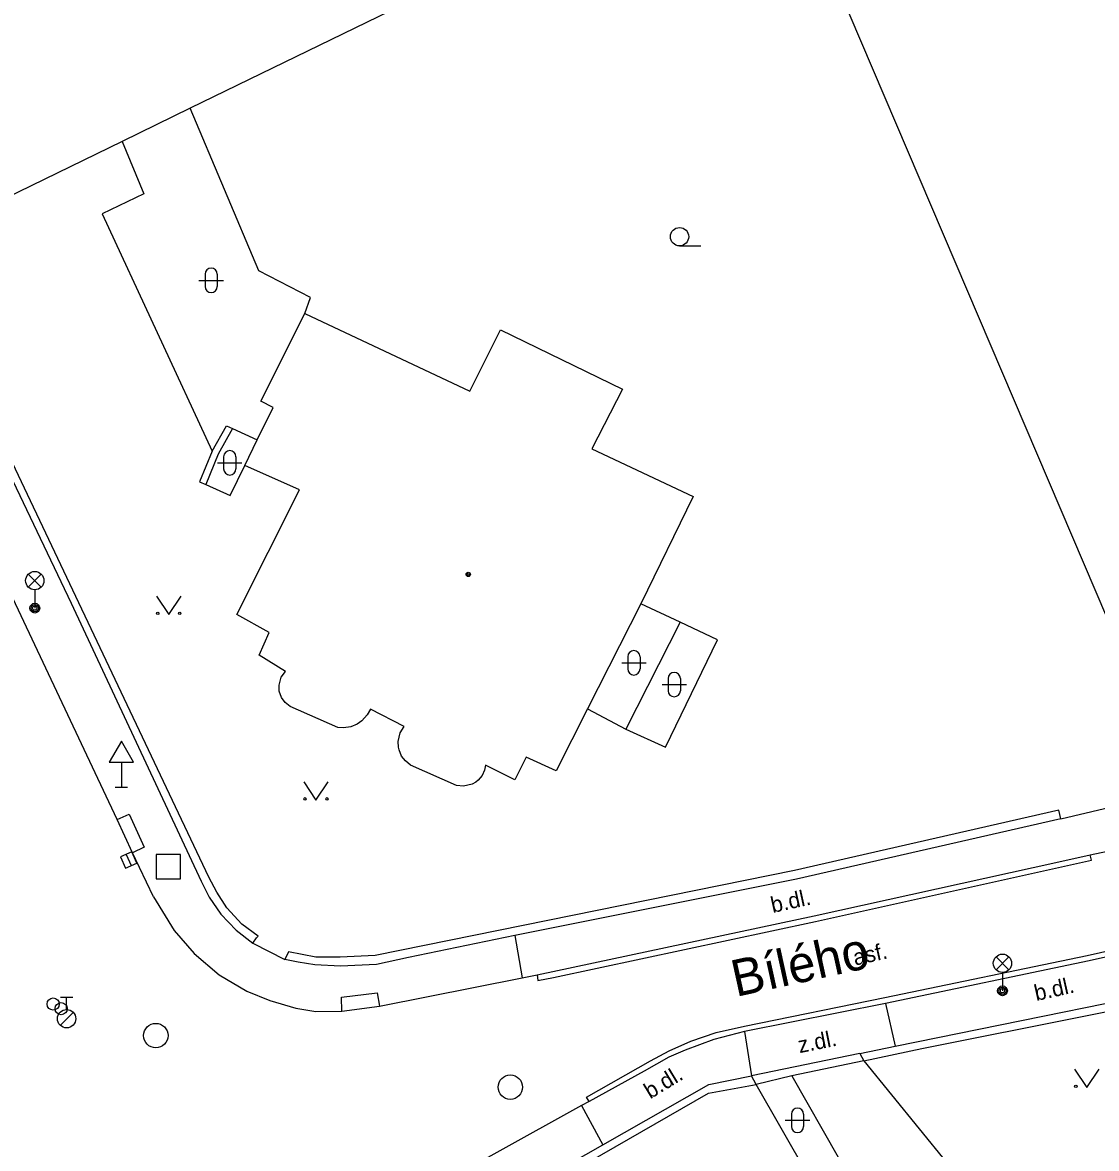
# Model space of a CAD drawing. Extents: x -600391 to -599491, y -1160176 to -1159402.
# Drawn here: x -600037.06 to -599993.14, y -1160099.55 to -1160053.5 of the extents above; entities that cross this region are included whole.
import ezdxf

# ---------------------------------------------------------------- set-up
doc = ezdxf.new("R2010")
doc.units = 0
for name, color, linetype in [('Level 10', 7, 'Continuous'), ('Level 11', 7, 'Continuous'), ('Level 26', 7, 'Continuous'), ('Level 27', 7, 'Continuous'), ('Level 28', 7, 'Continuous'), ('Level 33', 7, 'Continuous'), ('Level 34', 7, 'Continuous'), ('Level 36', 7, 'Continuous'), ('Level 39', 7, 'Continuous'), ('Level 40', 7, 'Continuous'), ('Level 5', 7, 'Continuous'), ('Level 50', 7, 'Continuous'), ('Level 51', 7, 'Continuous'), ('Level 7', 7, 'Continuous'), ('Level 8', 7, 'Continuous')]:
    doc.layers.add(name, color=color, linetype=linetype)

msp = doc.modelspace()

# ---------------------------------------------------------------- linework, layer by layer
at = {"layer": 'Level 10'}
for points in [[(-600033.19, -1160086.1), (-600042.96, -1160065.38), (-600049.67, -1160051.14), (-600054.09, -1160041.8), (-600054.53, -1160040.87)], [(-599993.39, -1160087.54), (-599991.01, -1160087.03), (-599990.646, -1160086.946), (-599984.87, -1160085.61), (-599971.12, -1160082.33), (-599968.6, -1160081.73), (-599966.29, -1160081.08)], [(-599964.94, -1160085.13), (-599967.7, -1160085.82), (-599969.78, -1160086.33), (-599971.99, -1160086.86), (-599984.11, -1160089.79), (-599993.43, -1160091.88), (-600001.76, -1160093.62)], [(-600032.57, -1160087.46), (-600033.19, -1160086.1)], [(-600031.71, -1160089.26), (-600032.57, -1160087.46)], [(-600016.01, -1160092.45), (-600004.68, -1160090.04), (-599994.67, -1160087.82), (-599993.39, -1160087.54)], [(-600031.71, -1160089.26), (-600030.86, -1160090.64), (-600030.04, -1160091.57), (-600029.02, -1160092.44), (-600027.89, -1160093.11), (-600026.94, -1160093.49), (-600025.89, -1160093.81), (-600025.07, -1160093.95)], [(-600022.46, -1160093.73), (-600016.63, -1160092.57)], [(-600016.63, -1160092.57), (-600016.01, -1160092.45)], [(-600025.07, -1160093.95), (-600024, -1160093.93)], [(-600024, -1160093.93), (-600022.46, -1160093.73)], [(-600001.76, -1160093.62), (-600007.53, -1160094.76)], [(-600007.53, -1160094.76), (-600008.78, -1160095.09), (-600009.96, -1160095.53), (-600010.63, -1160095.82), (-600011.63, -1160096.38), (-600013.88, -1160097.63)], [(-600013.88, -1160097.63), (-600014.2, -1160097.79)], [(-600014.2, -1160097.79), (-600021.25, -1160101.7)]]:
    msp.add_lwpolyline(points, dxfattribs=at)
at = {"layer": 'Level 11'}
for points in [[(-600010.17, -1160078.02), (-600011.77, -1160077.27)], [(-600010.17, -1160078.02), (-600012.39, -1160082.4)], [(-600012.39, -1160082.4), (-600010.76, -1160083.13), (-600008.63, -1160078.74), (-600010.17, -1160078.02)], [(-600013.96, -1160081.57), (-600012.39, -1160082.4)], [(-600033.19, -1160086.1), (-600032.7, -1160085.87), (-600032.08, -1160087.22), (-600032.57, -1160087.46)], [(-600016.01, -1160092.45), (-600015.98, -1160092.68), (-600015.34, -1160092.56), (-600004.63, -1160090.27), (-599993.34, -1160087.76), (-599993.39, -1160087.54)], [(-600013.88, -1160097.63), (-600014, -1160097.45), (-600011.38, -1160095.96), (-600010.62, -1160095.55), (-600009.73, -1160095.16), (-600008.69, -1160094.81), (-600007.53, -1160094.54), (-600001.79, -1160093.38), (-599993.52, -1160091.66), (-599984.18, -1160089.56)], [(-600016.93, -1160090.84), (-600016.63, -1160092.57)], [(-600024, -1160093.93), (-600024.02, -1160093.36), (-600022.56, -1160093.18), (-600022.46, -1160093.73)], [(-600001.76, -1160093.62), (-600001.37, -1160095.37)], [(-600007.53, -1160094.76), (-600007.25, -1160096.58)], [(-600002.65, -1160095.96), (-600005.59, -1160096.58)], [(-600002.65, -1160095.96), (-599999.26, -1160100.13)], [(-600005.59, -1160096.58), (-600007.05, -1160096.93)], [(-600005.59, -1160096.58), (-600003.7, -1160099.91)], [(-600004.95, -1160100.6), (-600007.05, -1160096.93)], [(-600014.2, -1160097.79), (-600013.33, -1160099.4)]]:
    msp.add_lwpolyline(points, dxfattribs=at)
at = {"layer": 'Level 26'}
msp.add_lwpolyline([(-600031.6, -1160088.52), (-600030.6, -1160088.52), (-600030.6, -1160087.52), (-600031.6, -1160087.52)], close=True, dxfattribs=at)
at = {"layer": 'Level 27'}
msp.add_line((-600032.822, -1160087.522), (-600032.617, -1160087.978), dxfattribs=at)
msp.add_lwpolyline([(-600033.05, -1160087.624), (-600032.846, -1160088.08), (-600032.389, -1160087.876), (-600032.594, -1160087.42)], close=True, dxfattribs=at)
for centre in [(-600031.61, -1160094.93), (-600017.11, -1160097.04)]:
    msp.add_circle(centre, 0.5, dxfattribs=at)
at = {"layer": 'Level 28'}
for p, q in [((-600035.51, -1160093.365), (-600035.01, -1160093.365)), ((-600035.26, -1160093.865), (-600035.26, -1160093.365)), ((-600035.518, -1160094.512), (-600034.988, -1160093.982))]:
    msp.add_line(p, q, dxfattribs=at)
for centre, radius in [((-600035.81, -1160093.64), 0.25), ((-600035.48, -1160093.83), 0.25), ((-600035.26, -1160094.24), 0.375)]:
    msp.add_circle(centre, radius, dxfattribs=at)
at = {"layer": 'Level 33'}
for p, q in [((-600036.825, -1160076.59), (-600036.295, -1160076.06)), ((-600036.825, -1160076.06), (-600036.295, -1160076.59)), ((-600036.56, -1160076.7), (-600036.56, -1160077.45)), ((-599997.245, -1160092.24), (-599996.715, -1160091.71)), ((-599997.245, -1160091.71), (-599996.715, -1160092.24)), ((-599996.98, -1160092.35), (-599996.98, -1160093.1))]:
    msp.add_line(p, q, dxfattribs=at)
for centre, radius in [((-600036.56, -1160076.325), 0.375), ((-600036.56, -1160077.45), 0.2), ((-600036.56, -1160077.45), 0.145), ((-600036.56, -1160077.45), 0.0876), ((-599996.98, -1160091.975), 0.375), ((-599996.98, -1160093.1), 0.2), ((-599996.98, -1160093.1), 0.145), ((-599996.98, -1160093.1), 0.0876)]:
    msp.add_circle(centre, radius, dxfattribs=at)
at = {"layer": 'Level 34'}
for p, q in [((-600033.02, -1160083.752), (-600033.02, -1160084.77)), ((-600033.27, -1160084.77), (-600032.77, -1160084.77))]:
    msp.add_line(p, q, dxfattribs=at)
msp.add_lwpolyline([(-600033.52, -1160083.752), (-600032.52, -1160083.752), (-600033.02, -1160082.886)], close=True, dxfattribs=at)
at = {"layer": 'Level 36'}
for p, q in [((-600010.19, -1160062.635), (-600009.315, -1160062.635)), ((-600029.846, -1160064.046), (-600028.846, -1160064.046)), ((-600029.596, -1160063.796), (-600029.596, -1160064.296)), ((-600029.096, -1160063.796), (-600029.096, -1160064.296)), ((-600028.836, -1160071.256), (-600028.836, -1160071.756)), ((-600028.336, -1160071.256), (-600028.336, -1160071.756)), ((-600029.086, -1160071.506), (-600028.086, -1160071.506)), ((-600012.556, -1160079.686), (-600011.556, -1160079.686)), ((-600012.306, -1160079.436), (-600012.306, -1160079.936)), ((-600011.806, -1160079.436), (-600011.806, -1160079.936)), ((-600010.906, -1160080.576), (-600009.906, -1160080.576)), ((-600010.656, -1160080.326), (-600010.656, -1160080.826)), ((-600010.156, -1160080.326), (-600010.156, -1160080.826)), ((-600005.616, -1160098.146), (-600005.616, -1160098.646)), ((-600005.116, -1160098.146), (-600005.116, -1160098.646)), ((-600005.866, -1160098.396), (-600004.866, -1160098.396))]:
    msp.add_line(p, q, dxfattribs=at)
for points in [[(-600031.58, -1160076.96), (-600031.08, -1160077.71), (-600030.58, -1160076.96)], [(-600025.56, -1160084.55), (-600025.06, -1160085.3), (-600024.56, -1160084.55)], [(-599994.03, -1160096.31), (-599993.53, -1160097.06), (-599993.03, -1160096.31)]]:
    msp.add_lwpolyline(points, dxfattribs=at)
for centre, radius in [((-600010.19, -1160062.26), 0.375), ((-600031.53, -1160077.66), 0.05), ((-600030.631, -1160077.66), 0.05), ((-600025.51, -1160085.25), 0.05), ((-600024.611, -1160085.25), 0.05), ((-599993.98, -1160097.01), 0.05)]:
    msp.add_circle(centre, radius, dxfattribs=at)
for centre, start, end in [((-600029.346, -1160063.796), 0, 180), ((-600029.346, -1160064.296), 180, 0), ((-600028.586, -1160071.256), 0, 180), ((-600028.586, -1160071.756), 180, 0), ((-600012.056, -1160079.436), 0, 180), ((-600012.056, -1160079.936), 180, 0), ((-600010.406, -1160080.326), 0, 180), ((-600010.406, -1160080.826), 180, 0), ((-600005.366, -1160098.146), 0, 180), ((-600005.366, -1160098.646), 180, 0)]:
    msp.add_arc(centre, 0.25, start, end, dxfattribs=at)
at = {"layer": 'Level 39'}
for radius in [0.09, 0.0398]:
    msp.add_circle((-600018.83, -1160076.07), radius, dxfattribs=at)
at = {"layer": 'Level 5'}
for points in [[(-600027.32, -1160068.98), (-600025.52, -1160065.4)], [(-600025.52, -1160065.4), (-600018.76, -1160068.58)], [(-600018.76, -1160068.58), (-600017.51, -1160066.07)], [(-600017.51, -1160066.07), (-600012.52, -1160068.49)], [(-600012.52, -1160068.49), (-600013.78, -1160070.93)], [(-600026.81, -1160069.24), (-600027.32, -1160068.98)], [(-600027.46, -1160070.57), (-600026.81, -1160069.24)], [(-600027.97, -1160071.61), (-600027.46, -1160070.57)], [(-600013.78, -1160070.93), (-600009.63, -1160072.89)], [(-600025.74, -1160072.61), (-600027.97, -1160071.61)], [(-600028.3, -1160077.71), (-600025.74, -1160072.61)], [(-600009.63, -1160072.89), (-600011.77, -1160077.27)], [(-600011.77, -1160077.27), (-600013.96, -1160081.57)], [(-600026.97, -1160078.44), (-600028.3, -1160077.71)], [(-600027.38, -1160079.37), (-600026.97, -1160078.44)], [(-600026.31, -1160080.04), (-600027.38, -1160079.37)], [(-600026.48, -1160080.27), (-600026.31, -1160080.04)], [(-600026.57, -1160080.6), (-600026.48, -1160080.27)], [(-600026.56, -1160080.85), (-600026.57, -1160080.6)], [(-600026.47, -1160081.1), (-600026.56, -1160080.85)], [(-600026.32, -1160081.31), (-600026.47, -1160081.1)], [(-600026.12, -1160081.47), (-600026.32, -1160081.31)], [(-600024.17, -1160082.33), (-600026.12, -1160081.47)], [(-600022.83, -1160081.58), (-600022.96, -1160081.82)], [(-600021.45, -1160082.29), (-600022.83, -1160081.58)], [(-600013.96, -1160081.57), (-600015.23, -1160084.1)], [(-600023.18, -1160082.06), (-600023.37, -1160082.19)], [(-600022.96, -1160081.82), (-600023.18, -1160082.06)], [(-600023.93, -1160082.35), (-600024.17, -1160082.33)], [(-600023.63, -1160082.3), (-600023.93, -1160082.35)], [(-600023.37, -1160082.19), (-600023.63, -1160082.3)], [(-600021.61, -1160082.55), (-600021.45, -1160082.29)], [(-600021.7, -1160082.91), (-600021.61, -1160082.55)], [(-600021.68, -1160083.14), (-600021.7, -1160082.91)], [(-600021.66, -1160083.25), (-600021.68, -1160083.14)], [(-600021.56, -1160083.5), (-600021.66, -1160083.25)], [(-600021.4, -1160083.7), (-600021.56, -1160083.5)], [(-600021.19, -1160083.87), (-600021.4, -1160083.7)], [(-600019.31, -1160084.7), (-600021.19, -1160083.87)], [(-600018.12, -1160083.87), (-600018.16, -1160084.08)], [(-600016.93, -1160084.47), (-600018.12, -1160083.87)], [(-600016.46, -1160083.55), (-600016.93, -1160084.47)], [(-600015.23, -1160084.1), (-600016.46, -1160083.55)], [(-600018.26, -1160084.29), (-600018.43, -1160084.49)], [(-600018.16, -1160084.08), (-600018.26, -1160084.29)], [(-600019.03, -1160084.73), (-600019.31, -1160084.7)], [(-600018.67, -1160084.65), (-600019.03, -1160084.73)], [(-600018.52, -1160084.57), (-600018.67, -1160084.65)], [(-600018.43, -1160084.49), (-600018.52, -1160084.57)]]:
    msp.add_lwpolyline(points, dxfattribs=at)
at = {"layer": 'Level 51'}
for points in [[(-600006.64, -1160045.18), (-599996.02, -1160070.07)], [(-600013.39, -1160048.82), (-600030.2, -1160057)], [(-600030.2, -1160057), (-600032.98, -1160058.36)], [(-600027.39, -1160063.65), (-600030.2, -1160057)], [(-600032.98, -1160058.36), (-600032.1, -1160060.51)], [(-600032.1, -1160060.51), (-600033.81, -1160061.32)], [(-600033.81, -1160061.32), (-600029.31, -1160071.03)], [(-600025.29, -1160064.74), (-600027.39, -1160063.65)], [(-600025.52, -1160065.4), (-600025.29, -1160064.74)], [(-600029.31, -1160071.03), (-600028.72, -1160069.99)], [(-600028.72, -1160069.99), (-600028.47, -1160070.11)], [(-600028.47, -1160070.11), (-600029.06, -1160071.15), (-600029.57, -1160072.4)], [(-600028.47, -1160070.11), (-600027.46, -1160070.57)], [(-600029.31, -1160071.03), (-600029.83, -1160072.28)], [(-600028.57, -1160072.85), (-600027.97, -1160071.61)], [(-600029.83, -1160072.28), (-600029.57, -1160072.4)], [(-600029.57, -1160072.4), (-600028.57, -1160072.85)]]:
    msp.add_lwpolyline(points, dxfattribs=at)
at = {"layer": 'Level 7'}
for points in [[(-600032.98, -1160058.36), (-600041.53, -1160062.53), (-600041.68, -1160062.64)], [(-600029.44, -1160088.45), (-600041.68, -1160062.64)], [(-600041.96, -1160062.84), (-600035.07, -1160077.24), (-600029.76, -1160088.61), (-600029.43, -1160089.27), (-600028.95, -1160089.96), (-600028.33, -1160090.62), (-600027.64, -1160091.15)], [(-599996.02, -1160070.07), (-599989.86, -1160084.51)], [(-599994.67, -1160085.71), (-600005.49, -1160088.18), (-600022.64, -1160091.66), (-600024.07, -1160091.73), (-600025.07, -1160091.72), (-600026.18, -1160091.5)], [(-599994.59, -1160086.06), (-599994.67, -1160085.71)], [(-599994.59, -1160086.06), (-600005.41, -1160088.53), (-600016.93, -1160090.84)], [(-600027.43, -1160090.86), (-600028.09, -1160090.37), (-600028.7, -1160089.71), (-600029.12, -1160089.07), (-600029.44, -1160088.45)], [(-600027.64, -1160091.15), (-600027.49, -1160090.94), (-600027.43, -1160090.86)], [(-600016.93, -1160090.84), (-600021.27, -1160091.74), (-600022.59, -1160092.02), (-600024.06, -1160092.09), (-600025.11, -1160092.04), (-600025.79, -1160091.93), (-600026.33, -1160091.82)], [(-600026.18, -1160091.5), (-600026.33, -1160091.82)], [(-600001.37, -1160095.37), (-599986.74, -1160092.39)], [(-600002.65, -1160095.96), (-600000.28, -1160095.46), (-599986.69, -1160092.75)], [(-600002.82, -1160095.67), (-600001.37, -1160095.37)], [(-600002.82, -1160095.67), (-600002.65, -1160095.96)], [(-600008.99, -1160096.93), (-600007.25, -1160096.58)], [(-600007.05, -1160096.93), (-600007.25, -1160096.58)], [(-600011.5, -1160122.58), (-600021.64, -1160104.55), (-600009, -1160097.29), (-600007.05, -1160096.93)], [(-600013.33, -1160099.4), (-600008.99, -1160096.93)], [(-600022.27, -1160104.48), (-600013.33, -1160099.4)]]:
    msp.add_lwpolyline(points, dxfattribs=at)
at = {"layer": 'Level 8'}
for points in [[(-599994.59, -1160086.06), (-599991.54, -1160085.34)], [(-600027.64, -1160091.15), (-600026.33, -1160091.82)], [(-600002.82, -1160095.67), (-600007.25, -1160096.58)]]:
    msp.add_lwpolyline(points, dxfattribs=at)

# ---------------------------------------------------------------- texts
at = {"layer": 'Level 40'}
for s, rotation, p in [('b.dl. ', 12.5, (-600006.38, -1160089.92)), ('asf.', 12.53, (-600003.01, -1160092.07)), ('b.dl. ', 12.65, (-599995.6, -1160093.52)), ('z.dl.', 11.31, (-600005.28, -1160095.65)), ('b.dl. ', 31.32, (-600011.39, -1160097.54))]:
    msp.add_text(s, height=0.65, rotation=rotation, dxfattribs=at).set_placement(p)
at = {"layer": 'Level 50'}
msp.add_text('Bílého', height=1.5, rotation=12.3997, dxfattribs=at).set_placement((-600007.883, -1160093.355))

doc.saveas('drawing.dxf')
